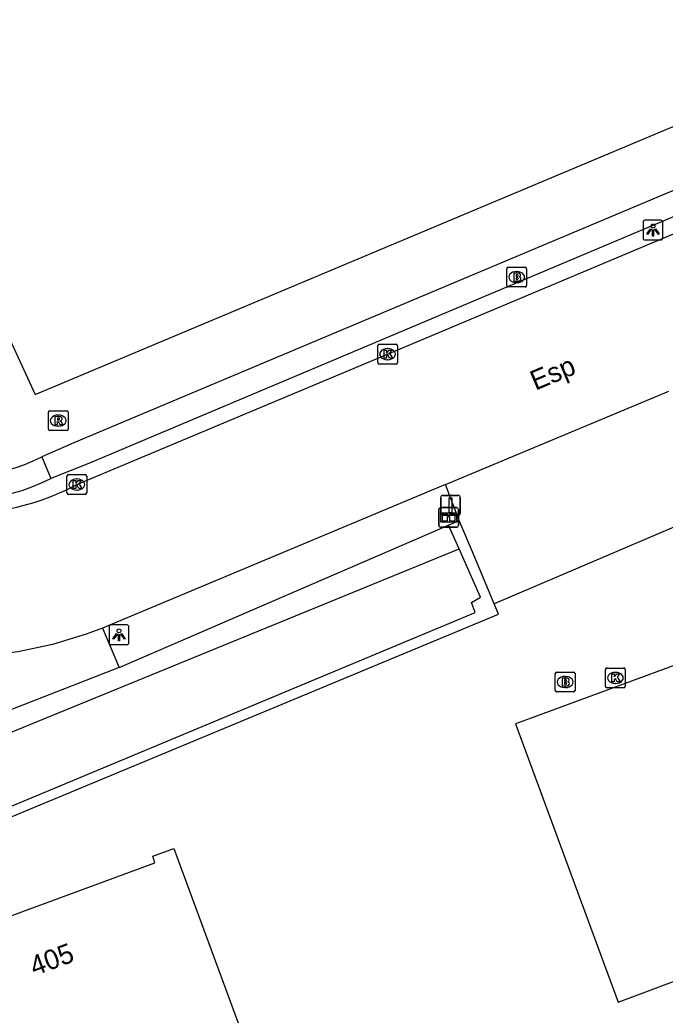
# Model space of a CAD drawing. Extents: x 161389 to 162585, y 388479 to 389761.
# Drawn here: x 162047.6 to 162080.2, y 388775.6 to 388826.1 of the extents above; entities that cross this region are included whole.
import ezdxf

# ---------------------------------------------------------------- set-up
doc = ezdxf.new("R2010")
doc.units = 0
for name, color, linetype in [('IMGEO_Afsluitpaal', 7, 'Continuous'), ('IMGEO_Berm_groen', 7, 'Continuous'), ('IMGEO_Brandkraan', 7, 'Continuous'), ('IMGEO_Informatiebord', 7, 'Continuous'), ('IMGEO_Kolk', 7, 'Continuous'), ('IMGEO_Lichtpunt', 7, 'Continuous'), ('IMGEO_Muur', 7, 'Continuous'), ('IMGEO_Openbare_ruimte_label', 7, 'Continuous'), ('IMGEO_Pand', 7, 'Continuous'), ('IMGEO_Pand_nummerreeks', 7, 'Continuous'), ('IMGEO_Pand_overbouw', 7, 'Continuous'), ('IMGEO_Rijbaan_lokaal_gesloten', 7, 'Continuous'), ('IMGEO_Rioolput', 7, 'Continuous'), ('IMGEO_Voetpad_open', 7, 'Continuous'), ('IMGEO_Waterloop', 7, 'Continuous')]:
    doc.layers.add(name, color=color, linetype=linetype)

msp = doc.modelspace()

# ---------------------------------------------------------------- linework, layer by layer
at = {"layer": 'IMGEO_Afsluitpaal'}
for p, q in [((162068.884, 388801.069), (162068.884, 388801.869)), ((162068.884, 388801.869), (162068.884, 388801.069)), ((162068.984, 388801.969), (162069.774, 388801.969)), ((162069.774, 388801.969), (162068.984, 388801.969)), ((162069.874, 388801.869), (162069.874, 388801.069)), ((162069.874, 388801.069), (162069.874, 388801.869)), ((162069.774, 388800.969), (162068.984, 388800.969)), ((162068.984, 388800.969), (162069.774, 388800.969))]:
    msp.add_line(p, q, dxfattribs=at)
msp.add_lwpolyline([(162069.304, 388801.844), (162069.454, 388801.844), (162069.454, 388801.094), (162069.304, 388801.094), (162069.304, 388801.844)], dxfattribs=at)
for centre, start, end in [((162068.984, 388801.869), 90, 180), ((162068.984, 388801.869), 90, 180), ((162069.774, 388801.869), 0, 90), ((162069.774, 388801.869), 360, 90), ((162068.984, 388801.069), 180, 270), ((162068.984, 388801.069), 180, 270), ((162069.774, 388801.069), 270, 0), ((162069.774, 388801.069), 270, 0)]:
    msp.add_arc(centre, 0.1, start, end, dxfattribs=at)
at = {"layer": 'IMGEO_Berm_groen'}
for points in [[(162052.609, 388793.254), (162069.544, 388800.58)], [(162051.757, 388795.247), (162052.609, 388793.254)], [(162052.609, 388793.254), (162034.299, 388786.108)]]:
    msp.add_lwpolyline(points, dxfattribs=at)
at = {"layer": 'IMGEO_Brandkraan'}
for p, q in [((162072.231, 388812.604), (162072.231, 388813.456)), ((162072.306, 388813.53), (162073.158, 388813.53)), ((162073.232, 388813.456), (162073.232, 388812.604)), ((162072.719, 388813.31), (162072.744, 388813.31)), ((162073.158, 388812.53), (162072.306, 388812.53)), ((162072.742, 388812.75), (162072.717, 388812.75)), ((162074.685, 388792.094), (162074.685, 388792.946)), ((162074.76, 388793.02), (162075.612, 388793.02)), ((162075.173, 388792.8), (162075.198, 388792.8)), ((162075.686, 388792.946), (162075.686, 388792.094)), ((162075.612, 388792.02), (162074.76, 388792.02)), ((162075.196, 388792.24), (162075.171, 388792.24))]:
    msp.add_line(p, q, dxfattribs=at)
for points in [[(162072.231, 388812.604), (162072.231, 388813.456)], [(162072.306, 388813.53), (162073.158, 388813.53)], [(162073.232, 388813.456), (162073.232, 388812.604)], [(162072.579, 388813.23), (162072.579, 388812.83), (162072.792, 388812.83)], [(162072.81, 388813.23), (162072.579, 388813.23)], [(162072.758, 388813.149), (162072.704, 388813.149), (162072.704, 388813.073)], [(162072.704, 388813.073), (162072.757, 388813.073)], [(162072.766, 388812.997), (162072.704, 388812.997), (162072.704, 388812.916)], [(162073.158, 388812.53), (162072.306, 388812.53)], [(162072.704, 388812.916), (162072.766, 388812.916)], [(162074.685, 388792.094), (162074.685, 388792.946)], [(162074.76, 388793.02), (162075.612, 388793.02)], [(162075.686, 388792.946), (162075.686, 388792.094)], [(162075.033, 388792.72), (162075.033, 388792.32), (162075.246, 388792.32)], [(162075.264, 388792.72), (162075.033, 388792.72)], [(162075.212, 388792.639), (162075.158, 388792.639), (162075.158, 388792.563)], [(162075.158, 388792.563), (162075.211, 388792.563)], [(162075.22, 388792.487), (162075.158, 388792.487), (162075.158, 388792.406)], [(162075.158, 388792.406), (162075.22, 388792.406)], [(162075.612, 388792.02), (162074.76, 388792.02)]]:
    msp.add_lwpolyline(points, dxfattribs=at)
for centre, radius, start, end in [((162072.308, 388813.454), 0.0765, 91.552, 178.448), ((162072.308, 388813.454), 0.0765, 91.552, 178.448), ((162073.156, 388813.454), 0.0765, 1.552, 88.448), ((162073.156, 388813.454), 0.0765, 1.552, 88.448), ((162072.759, 388813.111), 0.0379, 267.8285, 90.9355), ((162072.767, 388812.956), 0.0404, 269.8759, 90.5077), ((162072.814, 388813.085), 0.145, 59.4692, 91.5367), ((162072.839, 388813.132), 0.0922, 285.5137, 58.1501), ((162072.844, 388812.94), 0.105, 301.3115, 78.989), ((162072.308, 388812.606), 0.0765, 181.552, 268.448), ((162072.308, 388812.606), 0.0765, 181.552, 268.448), ((162072.798, 388813.081), 0.251, 268.6676, 293.5347), ((162073.156, 388812.606), 0.0765, 271.552, 358.448), ((162073.156, 388812.606), 0.0765, 271.552, 358.448), ((162074.762, 388792.944), 0.0765, 91.552, 178.448), ((162074.762, 388792.944), 0.0765, 91.552, 178.448), ((162075.61, 388792.944), 0.0765, 1.552, 88.448), ((162075.61, 388792.944), 0.0765, 1.552, 88.448), ((162075.213, 388792.601), 0.0379, 267.8285, 90.9355), ((162075.221, 388792.446), 0.0404, 269.8759, 90.5077), ((162075.252, 388792.571), 0.251, 268.6676, 293.5347), ((162075.268, 388792.575), 0.145, 59.4692, 91.5367), ((162075.293, 388792.622), 0.0922, 285.5137, 58.1501), ((162075.298, 388792.43), 0.105, 301.3115, 78.989), ((162074.762, 388792.096), 0.0765, 181.552, 268.448), ((162074.762, 388792.096), 0.0765, 181.552, 268.448), ((162075.61, 388792.096), 0.0765, 271.552, 358.448), ((162075.61, 388792.096), 0.0765, 271.552, 358.448)]:
    msp.add_arc(centre, radius, start, end, dxfattribs=at)
for centre, major_axis, ratio, start_param, end_param in [((162072.718, 388813.03), (-0.387, 0.002), 0.722429, 4.712389, 7.853982), ((162072.743, 388813.03), (-0.39, 0.002), 0.717154, 1.570796, 4.712389), ((162075.172, 388792.52), (-0.387, 0.002), 0.722429, 4.712389, 7.853982), ((162075.197, 388792.52), (-0.39, 0.002), 0.717154, 1.570796, 4.712389)]:
    msp.add_ellipse(centre, major_axis=major_axis, ratio=ratio, start_param=start_param, end_param=end_param, dxfattribs=at)
at = {"layer": 'IMGEO_Informatiebord'}
for p, q in [((162068.889, 388801.355), (162069.679, 388801.355)), ((162069.679, 388801.355), (162068.889, 388801.355)), ((162068.789, 388800.455), (162068.789, 388801.255)), ((162068.789, 388801.255), (162068.789, 388800.455)), ((162069.779, 388801.255), (162069.779, 388800.455)), ((162069.779, 388800.455), (162069.779, 388801.255)), ((162069.679, 388800.355), (162068.889, 388800.355)), ((162068.889, 388800.355), (162069.679, 388800.355))]:
    msp.add_line(p, q, dxfattribs=at)
for points in [[(162068.89, 388801.087), (162069.678, 388801.087), (162069.678, 388800.623), (162068.89, 388800.623), (162068.89, 388801.087)], [(162068.955, 388801.022), (162068.955, 388800.688), (162069.23, 388800.688), (162069.231, 388800.901), (162069.335, 388800.902), (162069.336, 388800.688), (162069.613, 388800.688), (162069.613, 388801.022), (162069.337, 388801.022), (162069.337, 388800.942), (162069.231, 388800.942), (162069.231, 388801.022), (162068.955, 388801.022)]]:
    msp.add_lwpolyline(points, dxfattribs=at)
for centre, start, end in [((162068.889, 388801.255), 90, 180), ((162068.889, 388801.255), 90, 180), ((162069.679, 388801.255), 0, 90), ((162069.679, 388801.255), 360, 90), ((162068.889, 388800.455), 180, 270), ((162068.889, 388800.455), 180, 270), ((162069.679, 388800.455), 270, 0), ((162069.679, 388800.455), 270, 0)]:
    msp.add_arc(centre, 0.1, start, end, dxfattribs=at)
at = {"layer": 'IMGEO_Kolk'}
for p, q in [((162065.694, 388808.702), (162065.694, 388809.554)), ((162065.769, 388809.628), (162066.621, 388809.628)), ((162066.182, 388809.408), (162066.207, 388809.408)), ((162066.695, 388809.554), (162066.695, 388808.702)), ((162066.621, 388808.628), (162065.769, 388808.628)), ((162066.205, 388808.848), (162066.18, 388808.848)), ((162049.965, 388802.098), (162049.965, 388802.95)), ((162050.04, 388803.024), (162050.892, 388803.024)), ((162050.966, 388802.95), (162050.966, 388802.098)), ((162050.453, 388802.804), (162050.478, 388802.804)), ((162050.892, 388802.024), (162050.04, 388802.024)), ((162050.476, 388802.244), (162050.451, 388802.244)), ((162077.226, 388792.303), (162077.226, 388793.155)), ((162077.301, 388793.229), (162078.153, 388793.229)), ((162077.714, 388793.009), (162077.739, 388793.009)), ((162078.227, 388793.155), (162078.227, 388792.303)), ((162077.737, 388792.449), (162077.712, 388792.449)), ((162078.153, 388792.229), (162077.301, 388792.229))]:
    msp.add_line(p, q, dxfattribs=at)
for points in [[(162065.694, 388808.702), (162065.694, 388809.554)], [(162065.769, 388809.628), (162066.621, 388809.628)], [(162066.695, 388809.554), (162066.695, 388808.702)], [(162066.015, 388809.328), (162066.138, 388809.328), (162066.138, 388809.177), (162066.268, 388809.328), (162066.432, 388809.328), (162066.286, 388809.177), (162066.439, 388808.928), (162066.287, 388808.928), (162066.202, 388809.092), (162066.138, 388809.025), (162066.138, 388808.928), (162066.015, 388808.928), (162066.015, 388809.328)], [(162066.621, 388808.628), (162065.769, 388808.628)], [(162049.965, 388802.098), (162049.965, 388802.95)], [(162050.04, 388803.024), (162050.892, 388803.024)], [(162050.966, 388802.95), (162050.966, 388802.098)], [(162050.286, 388802.724), (162050.409, 388802.724), (162050.409, 388802.573), (162050.539, 388802.724), (162050.703, 388802.724), (162050.557, 388802.573), (162050.71, 388802.324), (162050.558, 388802.324), (162050.473, 388802.488), (162050.409, 388802.421), (162050.409, 388802.324), (162050.286, 388802.324), (162050.286, 388802.724)], [(162050.892, 388802.024), (162050.04, 388802.024)], [(162077.226, 388792.303), (162077.226, 388793.155)], [(162077.301, 388793.229), (162078.153, 388793.229)], [(162077.547, 388792.929), (162077.67, 388792.929), (162077.67, 388792.778), (162077.8, 388792.929), (162077.964, 388792.929), (162077.818, 388792.778), (162077.971, 388792.529), (162077.819, 388792.529), (162077.734, 388792.693), (162077.67, 388792.626), (162077.67, 388792.529), (162077.547, 388792.529), (162077.547, 388792.929)], [(162078.227, 388793.155), (162078.227, 388792.303)], [(162078.153, 388792.229), (162077.301, 388792.229)]]:
    msp.add_lwpolyline(points, dxfattribs=at)
for centre, start, end in [((162065.771, 388809.552), 91.552, 178.448), ((162065.771, 388809.552), 91.552, 178.448), ((162066.619, 388809.552), 1.552, 88.448), ((162066.619, 388809.552), 1.552, 88.448), ((162065.771, 388808.704), 181.552, 268.448), ((162065.771, 388808.704), 181.552, 268.448), ((162066.619, 388808.704), 271.552, 358.448), ((162066.619, 388808.704), 271.552, 358.448), ((162050.042, 388802.948), 91.552, 178.448), ((162050.042, 388802.948), 91.552, 178.448), ((162050.89, 388802.948), 1.552, 88.448), ((162050.89, 388802.948), 1.552, 88.448), ((162050.042, 388802.1), 181.552, 268.448), ((162050.042, 388802.1), 181.552, 268.448), ((162050.89, 388802.1), 271.552, 358.448), ((162050.89, 388802.1), 271.552, 358.448), ((162077.303, 388793.153), 91.552, 178.448), ((162077.303, 388793.153), 91.552, 178.448), ((162078.151, 388793.153), 1.552, 88.448), ((162078.151, 388793.153), 1.552, 88.448), ((162077.303, 388792.305), 181.552, 268.448), ((162077.303, 388792.305), 181.552, 268.448), ((162078.151, 388792.305), 271.552, 358.448), ((162078.151, 388792.305), 271.552, 358.448)]:
    msp.add_arc(centre, 0.0765, start, end, dxfattribs=at)
for centre, major_axis, ratio, start_param, end_param in [((162066.181, 388809.128), (-0.387, 0.002), 0.722429, 4.712389, 7.853982), ((162066.206, 388809.128), (-0.39, 0.002), 0.717154, 1.570796, 4.712389), ((162050.452, 388802.524), (-0.387, 0.002), 0.722429, 4.712389, 7.853982), ((162050.477, 388802.524), (-0.39, 0.002), 0.717154, 1.570796, 4.712389), ((162077.713, 388792.729), (-0.387, 0.002), 0.722429, 4.712389, 7.853982), ((162077.738, 388792.729), (-0.39, 0.002), 0.717154, 1.570796, 4.712389)]:
    msp.add_ellipse(centre, major_axis=major_axis, ratio=ratio, start_param=start_param, end_param=end_param, dxfattribs=at)
at = {"layer": 'IMGEO_Lichtpunt'}
for p, q in [((162079.129, 388815.817), (162079.129, 388815.01)), ((162079.129, 388815.817), (162079.129, 388815.01)), ((162080.031, 388815.912), (162079.223, 388815.912)), ((162080.031, 388815.912), (162079.223, 388815.912)), ((162080.125, 388815.01), (162080.125, 388815.817)), ((162080.125, 388815.01), (162080.125, 388815.817)), ((162079.223, 388814.916), (162080.031, 388814.916)), ((162079.223, 388814.916), (162080.031, 388814.916)), ((162052.101, 388795.313), (162052.101, 388794.506)), ((162052.101, 388795.313), (162052.101, 388794.506)), ((162053.003, 388795.408), (162052.195, 388795.408)), ((162053.003, 388795.408), (162052.195, 388795.408)), ((162053.097, 388794.506), (162053.097, 388795.313)), ((162053.097, 388794.506), (162053.097, 388795.313)), ((162052.195, 388794.412), (162053.003, 388794.412)), ((162052.195, 388794.412), (162053.003, 388794.412))]:
    msp.add_line(p, q, dxfattribs=at)
for points in [[(162079.503, 388815.481), (162079.542, 388815.453), (162079.354, 388815.191), (162079.316, 388815.218), (162079.503, 388815.481)], [(162079.715, 388815.453), (162079.753, 388815.48), (162079.94, 388815.218), (162079.901, 388815.19), (162079.715, 388815.453)], [(162079.605, 388815.433), (162079.652, 388815.433), (162079.652, 388815.111), (162079.605, 388815.111), (162079.605, 388815.433)], [(162052.475, 388794.977), (162052.514, 388794.949), (162052.326, 388794.687), (162052.288, 388794.714), (162052.475, 388794.977)], [(162052.577, 388794.929), (162052.624, 388794.929), (162052.624, 388794.607), (162052.577, 388794.607), (162052.577, 388794.929)], [(162052.687, 388794.949), (162052.725, 388794.976), (162052.912, 388794.714), (162052.873, 388794.686), (162052.687, 388794.949)]]:
    msp.add_lwpolyline(points, dxfattribs=at)
for centre in [(162079.628, 388815.615), (162052.6, 388795.111)]:
    msp.add_circle(centre, 0.0994, dxfattribs=at)
for centre, start, end in [((162079.223, 388815.817), 90, 180), ((162079.223, 388815.817), 90, 180), ((162080.031, 388815.817), 0, 90), ((162080.031, 388815.817), 0, 90), ((162079.223, 388815.01), 180, 270), ((162079.223, 388815.01), 180, 270), ((162080.031, 388815.01), 270, 0), ((162080.031, 388815.01), 270, 360), ((162052.195, 388795.313), 90, 180), ((162052.195, 388795.313), 90, 180), ((162053.003, 388795.313), 0, 90), ((162053.003, 388795.313), 0, 90), ((162052.195, 388794.506), 180, 270), ((162052.195, 388794.506), 180, 270), ((162053.003, 388794.506), 270, 0), ((162053.003, 388794.506), 270, 360)]:
    msp.add_arc(centre, 0.0946, start, end, dxfattribs=at)
at = {"layer": 'IMGEO_Muur'}
for points in [[(162069.817, 388799.258), (162069.286, 388800.465), (162069.544, 388800.58)], [(162069.544, 388800.58), (162069.823, 388800.704)], [(162071.588, 388796.475), (162070.621, 388798.791), (162069.823, 388800.704)], [(162035.905, 388781.533), (162070.625, 388796.045), (162070.443, 388796.555), (162070.892, 388796.816), (162070.117, 388798.576), (162069.817, 388799.258)], [(162035.905, 388781.533), (162036.191, 388781.141), (162037.233, 388781.575), (162071.804, 388795.956), (162071.588, 388796.475)]]:
    msp.add_lwpolyline(points, dxfattribs=at)
at = {"layer": 'IMGEO_Pand'}
for points in [[(162045.228, 388813.835), (162048.347, 388807.09), (162093.508, 388826.06)], [(162065.669, 388750), (162066.202, 388748.564), (162054.165, 388744.117), (162051.983, 388750), (162051.56, 388751.141), (162044.081, 388771.555), (162042.814, 388774.988), (162041.363, 388778.904), (162042.412, 388779.283), (162042.532, 388778.983), (162054.417, 388783.358), (162054.316, 388783.692), (162055.373, 388784.083), (162063.149, 388762.982), (162061.118, 388762.233), (162063.596, 388755.586), (162065.669, 388750)]]:
    msp.add_lwpolyline(points, dxfattribs=at)
at = {"layer": 'IMGEO_Pand_overbouw'}
msp.add_lwpolyline([(162084.904, 388794.91), (162083.664, 388794.453), (162073.411, 388790.673), (162072.666, 388790.398), (162077.866, 388776.304), (162078.586, 388776.573), (162088.806, 388780.397), (162090.149, 388780.9)], close=True, dxfattribs=at)
at = {"layer": 'IMGEO_Rijbaan_lokaal_gesloten'}
for points in [[(162050.467, 388802.522), (162066.195, 388809.127), (162083.964, 388816.605), (162092.793, 388820.3)], [(162051.757, 388795.247), (162050.936, 388794.936), (162049.238, 388794.418), (162047.501, 388794.055), (162045.738, 388793.848), (162043.963, 388793.799), (162043.524, 388793.814), (162041.903, 388793.961), (162040.302, 388794.252), (162038.733, 388794.686), (162037.209, 388795.257), (162035.743, 388795.963), (162034.345, 388796.797), (162033.028, 388797.752), (162031.8, 388798.821), (162030.674, 388799.995), (162029.657, 388801.266), (162028.757, 388802.622), (162027.982, 388804.053), (162024.808, 388810.847)], [(162069.13, 388802.525), (162072.726, 388804.031), (162080.428, 388807.257)], [(162069.13, 388802.525), (162051.757, 388795.247)]]:
    msp.add_lwpolyline(points, dxfattribs=at)
msp.add_arc((162044.489, 388813.812), 12.775, 251.1913, 297.9028, dxfattribs=at)
at = {"layer": 'IMGEO_Rioolput'}
for p, q in [((162049.021, 388805.335), (162049.021, 388806.187)), ((162049.096, 388806.261), (162049.948, 388806.261)), ((162049.509, 388806.041), (162049.534, 388806.041)), ((162050.022, 388806.187), (162050.022, 388805.335)), ((162049.532, 388805.481), (162049.507, 388805.481)), ((162049.948, 388805.261), (162049.096, 388805.261))]:
    msp.add_line(p, q, dxfattribs=at)
for points in [[(162049.021, 388805.335), (162049.021, 388806.187)], [(162049.096, 388806.261), (162049.948, 388806.261)], [(162049.61, 388805.959), (162049.358, 388805.961), (162049.358, 388805.561)], [(162049.536, 388805.88), (162049.482, 388805.88), (162049.482, 388805.799)], [(162050.022, 388806.187), (162050.022, 388805.335)], [(162049.358, 388805.561), (162049.482, 388805.561), (162049.482, 388805.723), (162049.493, 388805.723)], [(162049.482, 388805.799), (162049.534, 388805.799)], [(162049.54, 388805.694), (162049.611, 388805.561), (162049.751, 388805.561), (162049.686, 388805.687)], [(162049.948, 388805.261), (162049.096, 388805.261)]]:
    msp.add_lwpolyline(points, dxfattribs=at)
for centre, radius, start, end in [((162049.098, 388806.185), 0.0765, 91.552, 178.448), ((162049.098, 388806.185), 0.0765, 91.552, 178.448), ((162049.542, 388805.784), 0.0964, 77.0061, 93.1865), ((162049.556, 388805.841), 0.0378, 276.6634, 79.6772), ((162049.609, 388805.849), 0.109, 350.3612, 89.416), ((162049.946, 388806.185), 0.0765, 1.552, 88.448), ((162049.946, 388806.185), 0.0765, 1.552, 88.448), ((162049.492, 388805.67), 0.0533, 26.0293, 88.6989), ((162049.518, 388805.988), 0.19, 274.7715, 282.9687), ((162049.607, 388805.849), 0.112, 277.5842, 350.9817), ((162049.591, 388805.634), 0.108, 29.5134, 73.7905), ((162049.098, 388805.337), 0.0765, 181.552, 268.448), ((162049.098, 388805.337), 0.0765, 181.552, 268.448), ((162049.946, 388805.337), 0.0765, 271.552, 358.448), ((162049.946, 388805.337), 0.0765, 271.552, 358.448)]:
    msp.add_arc(centre, radius, start, end, dxfattribs=at)
for centre, major_axis, ratio, start_param, end_param in [((162049.508, 388805.761), (-0.387, 0.002), 0.722429, 4.712389, 7.853982), ((162049.533, 388805.761), (-0.39, 0.002), 0.717154, 1.570796, 4.712389)]:
    msp.add_ellipse(centre, major_axis=major_axis, ratio=ratio, start_param=start_param, end_param=end_param, dxfattribs=at)
at = {"layer": 'IMGEO_Voetpad_open'}
for points in [[(162091.45, 388821.953), (162050.304, 388804.628), (162048.684, 388803.926)], [(162091.936, 388820.838), (162051.101, 388803.612), (162049.152, 388802.833)], [(162048.684, 388803.926), (162049.152, 388802.833)], [(162069.823, 388800.704), (162069.13, 388802.525)], [(162082.695, 388801.152), (162081.388, 388800.675), (162075.936, 388798.339), (162071.588, 388796.475)]]:
    msp.add_lwpolyline(points, dxfattribs=at)
for centre, radius, start, end in [((162044.507, 388812.03), 9.117, 203.5706, 297.2683), ((162044.489, 388812.031), 10.313, 203.756, 296.8818)]:
    msp.add_arc(centre, radius, start, end, dxfattribs=at)
at = {"layer": 'IMGEO_Waterloop'}
msp.add_lwpolyline([(162034.727, 388784.889), (162069.817, 388799.258)], dxfattribs=at)

# ---------------------------------------------------------------- texts
at = {"layer": 'IMGEO_Openbare_ruimte_label'}
msp.add_text('Esp', height=1, rotation=22.7169, dxfattribs=at).set_placement((162073.678, 388807.274))
at = {"layer": 'IMGEO_Pand_nummerreeks'}
msp.add_text('405', height=1, rotation=20.209, dxfattribs=at).set_placement((162048.314, 388777.617))

doc.saveas('drawing.dxf')
